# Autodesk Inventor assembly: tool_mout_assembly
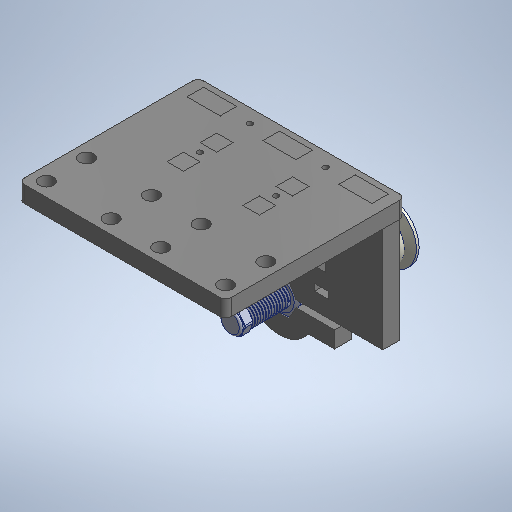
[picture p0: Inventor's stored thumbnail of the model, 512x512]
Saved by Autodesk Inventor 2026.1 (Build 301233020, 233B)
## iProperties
Created: 2026-10
Part Number: tool_mout_assembly
Document SubType Name: Assembly
Designer: hp
Author: hp
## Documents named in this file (7)
- C:\Users\hp\Documents\Inventor\DOM1_CartesianRobot\tool_mout_assembly.iam
- C:\Users\hp\Documents\Inventor\DOM1_CartesianRobot\tool_mount_part1.ipt
- C:\Users\hp\Documents\Inventor\DOM1_CartesianRobot\tool_mount_part2.ipt
- C:\Users\hp\Documents\Inventor\DOM1_CartesianRobot\tool_mount_part3.ipt
- C:\Users\hp\Documents\Inventor\DOM1_CartesianRobot\rip_5.ipt
- C:\Users\hp\Documents\Inventor\DOM1_CartesianRobot\rip_6.ipt
- C:\Users\hp\Documents\Inventor\DOM1_CartesianRobot\VACUUM NOZZLE.ipt
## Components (6 placed, 5 different names)
1. tool_mount_part1:1 — Mate:1, Mate:2, Flush:1, Mate:3, Mate:4, Flush:2, Mate:5, Mate:6, Mate:7, Flush:3
2. tool_mount_part2:1 — Mate:5, Mate:6, Mate:7, Flush:3, Flush:4, Angle:1, Mate:8, Mate:9, Flush:5
3. tool_mount_part3:1 — Flush:4, Mate:10, Mate:11
4. rip:1 — Mate:1, Mate:2, Flush:1
5. rip:2 — Mate:3, Mate:4, Flush:2
6. VACUUM NOZZLE:1 — Angle:1, Mate:8, Mate:9, Flush:5, Mate:10, Mate:11
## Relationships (17: Mate 11, Flush 5, Angle 1)
- Mate:1: tool_mount_part1:1 ↔ rip:1
- Mate:2: tool_mount_part1:1 ↔ rip:1
- Flush:1: tool_mount_part1:1 ↔ rip:1
- Mate:3: tool_mount_part1:1 ↔ rip:2
- Mate:4: tool_mount_part1:1 ↔ rip:2
- Flush:2: tool_mount_part1:1 ↔ rip:2
- Mate:5: tool_mount_part1:1 ↔ tool_mount_part2:1
- Mate:6: tool_mount_part1:1 ↔ tool_mount_part2:1
- Mate:7: tool_mount_part1:1 ↔ tool_mount_part2:1
- Flush:3: tool_mount_part1:1 ↔ tool_mount_part2:1
- Flush:4: tool_mount_part2:1 ↔ tool_mount_part3:1
- Angle:1: tool_mount_part2:1 ↔ VACUUM NOZZLE:1
- Mate:8: tool_mount_part2:1 ↔ VACUUM NOZZLE:1
- Mate:9: tool_mount_part2:1 ↔ VACUUM NOZZLE:1
- Flush:5: tool_mount_part2:1 ↔ VACUUM NOZZLE:1
- Mate:10: tool_mount_part3:1 ↔ VACUUM NOZZLE:1
- Mate:11: tool_mount_part3:1 ↔ VACUUM NOZZLE:1
